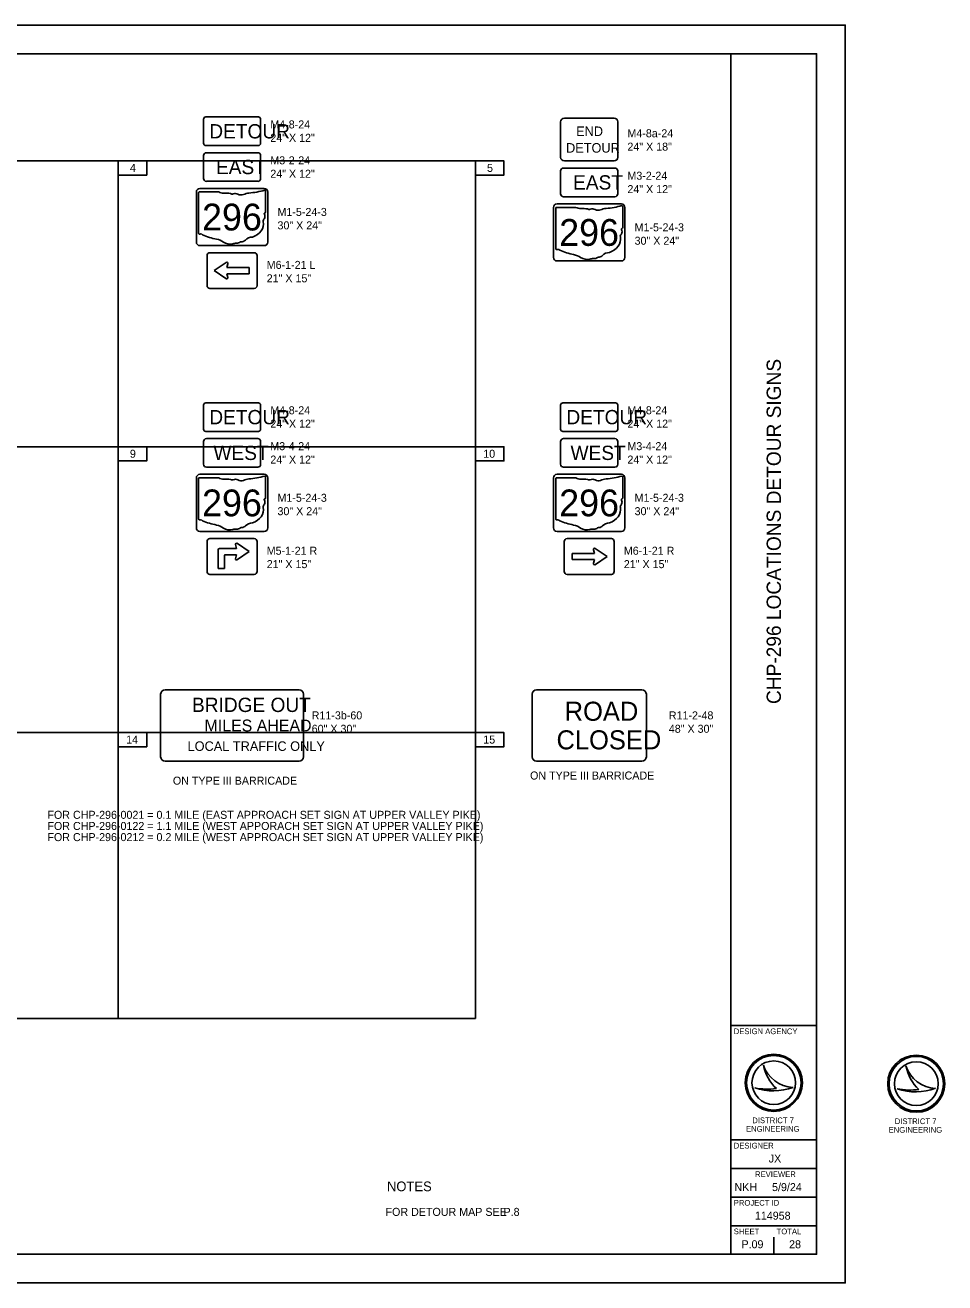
# Model space of a CAD drawing. Extents: x 0 to 715, y 0 to 440.
# Drawn here: x 393 to 714.9, y 0 to 440 of the extents above; entities that cross this region are included whole.
import ezdxf

# ---------------------------------------------------------------- set-up
doc = ezdxf.new("R2010")
doc.units = 0
for name, color, linetype in [('SC_Scratch1', 7, 'Continuous'), ('SH_Border', 7, 'Continuous'), ('SH_Cut_Line', 7, 'Continuous'), ('SH_Data', 7, 'Continuous'), ('SH_Text', 7, 'Continuous'), ('SN_P_Signs', 7, 'Continuous'), ('SN_P_Text', 7, 'Continuous')]:
    doc.layers.add(name, color=color, linetype=linetype)

msp = doc.modelspace()

# ---------------------------------------------------------------- linework, layer by layer
at = {"layer": 'SC_Scratch1'}
for p, q in [((375.54, 392.53), (550.54, 392.53)), ((425.54, 392.53), (425.54, 292.53)), ((550.54, 392.53), (550.54, 292.53)), ((375.54, 292.53), (550.54, 292.53)), ((425.54, 292.53), (425.54, 192.53)), ((550.54, 292.53), (550.54, 192.53)), ((375.54, 192.53), (550.54, 192.53)), ((425.54, 192.53), (425.54, 92.53)), ((550.54, 192.53), (550.54, 92.53)), ((375.54, 92.53), (550.54, 92.53))]:
    msp.add_line(p, q, dxfattribs=at)
at = {"layer": 'SH_Border'}
for p, q in [((640, 10), (640, 430)), ((640, 90), (670, 90)), ((640, 50), (670, 50)), ((640, 40), (670, 40)), ((640, 30), (670, 30)), ((640, 20), (670, 20))]:
    msp.add_line(p, q, dxfattribs=at)
msp.add_lwpolyline([(30, 430), (670, 430), (670, 10), (30, 10)], close=True, dxfattribs=at)
at = {"layer": 'SH_Cut_Line'}
msp.add_lwpolyline([(0, 0), (680, 0), (680, 440), (0, 440)], close=True, dxfattribs=at)
at = {"layer": 'SH_Data'}
for p, q in [((651.35, 76.19), (651.35, 76.19)), ((701.23, 75.87), (701.23, 75.87)), ((648.34, 68.19), (648.34, 68.19)), ((655, 70), (655, 70)), ((661.75, 68.37), (661.75, 68.37)), ((698.23, 67.87), (698.23, 67.87)), ((711.63, 68.05), (711.63, 68.05)), ((647.5, 13.5), (647.5, 13.5)), ((655, 10), (655, 16))]:
    msp.add_line(p, q, dxfattribs=at)
for centre, radius in [((655, 70), 10), ((655, 70), 9.54), ((655, 70), 9.54), ((704.88, 69.68), 10), ((704.88, 69.68), 9.54), ((704.88, 69.68), 9.54), ((655, 70), 7.64), ((704.88, 69.68), 7.64)]:
    msp.add_circle(centre, radius, dxfattribs=at)
for centre, radius, start, end in [((662.32, 79.95), 11.6, 198.9257, 198.9319), ((666.93, 79.4), 15.91, 191.6379, 191.6421), ((662.32, 79.95), 11.6, 198.9319, 267.1657), ((666.93, 79.4), 15.91, 191.6421, 226.0947), ((712.2, 79.63), 11.6, 198.9257, 198.9319), ((716.82, 79.08), 15.91, 191.6379, 191.6421), ((712.2, 79.63), 11.6, 198.9319, 267.1657), ((716.82, 79.08), 15.91, 191.6421, 226.0947), ((654.79, 87.4), 20.26, 251.4576, 290.0832), ((652.96, 93.09), 25.32, 259.4964, 259.4995), ((654.79, 87.4), 20.26, 251.4527, 251.4576), ((652.96, 93.09), 25.32, 259.4995, 276.6672), ((704.67, 87.08), 20.26, 251.4576, 290.0832), ((702.84, 92.77), 25.32, 259.4964, 259.4995), ((704.67, 87.08), 20.26, 251.4527, 251.4576), ((702.84, 92.77), 25.32, 259.4995, 276.6672)]:
    msp.add_arc(centre, radius, start, end, dxfattribs=at)
at = {"layer": 'SH_Text'}
for points in [[(425.54, 392.53), (435.54, 392.53), (435.54, 387.53), (425.54, 387.53)], [(550.54, 392.53), (560.54, 392.53), (560.54, 387.53), (550.54, 387.53)], [(425.54, 292.53), (435.54, 292.53), (435.54, 287.53), (425.54, 287.53)], [(550.54, 292.53), (560.54, 292.53), (560.54, 287.53), (550.54, 287.53)], [(425.54, 192.53), (435.54, 192.53), (435.54, 187.53), (425.54, 187.53)], [(550.54, 192.53), (560.54, 192.53), (560.54, 187.53), (550.54, 187.53)]]:
    msp.add_lwpolyline(points, close=True, dxfattribs=at)
at = {"layer": 'SN_P_Signs'}
for p, q in [((455.39, 386.37), (455.39, 394.37)), ((456.39, 395.37), (474.39, 395.37)), ((475.39, 394.37), (475.39, 386.37)), ((580.39, 380.99), (580.39, 388.99)), ((581.39, 389.99), (599.39, 389.99)), ((600.39, 388.99), (600.39, 380.99)), ((474.39, 385.37), (456.39, 385.37)), ((453.67, 381.39), (453.67, 367.16)), ((460.76, 381.64), (453.9, 381.64)), ((477.11, 374.55), (477.11, 381.99)), ((599.39, 379.99), (581.39, 379.99)), ((477.1, 374.55), (477.11, 374.55)), ((578.67, 376.02), (578.67, 361.79)), ((585.76, 376.26), (578.9, 376.26)), ((602.11, 369.17), (602.11, 376.61)), ((602.1, 369.17), (602.11, 369.17)), ((456.64, 359.37), (456.64, 348.87)), ((473.14, 360.37), (457.64, 360.37)), ((459.14, 354.12), (463.28, 356.96)), ((463.91, 356.49), (463.51, 355.21)), ((473.14, 360.37), (473.14, 360.37)), ((474.14, 348.87), (474.14, 359.37)), ((463.22, 351.32), (459.14, 354.12)), ((463.51, 355.21), (471.32, 355.21)), ((471.32, 353.02), (463.51, 353.02)), ((463.51, 353.02), (463.91, 351.74)), ((471.32, 355.21), (471.32, 353.02)), ((457.64, 347.87), (473.14, 347.87)), ((456.39, 295.37), (474.39, 295.37)), ((581.39, 295.37), (599.39, 295.37)), ((455.39, 286.37), (455.39, 294.37)), ((475.39, 294.37), (475.39, 286.37)), ((580.39, 286.37), (580.39, 294.37)), ((600.39, 294.37), (600.39, 286.37)), ((460.76, 281.64), (453.9, 281.64)), ((474.39, 285.37), (456.39, 285.37)), ((477.11, 274.55), (477.11, 281.99)), ((585.76, 281.64), (578.9, 281.64)), ((599.39, 285.37), (581.39, 285.37)), ((602.11, 274.55), (602.11, 281.99)), ((453.67, 281.39), (453.67, 267.16)), ((578.67, 281.39), (578.67, 267.16)), ((477.1, 274.55), (477.11, 274.55)), ((602.1, 274.55), (602.11, 274.55)), ((473.14, 260.37), (457.64, 260.37)), ((582.64, 260.37), (598.14, 260.37)), ((456.64, 259.37), (456.64, 248.87)), ((460.54, 249.9), (460.54, 256.46)), ((461.01, 256.93), (466.95, 256.93)), ((461.01, 256.93), (461.01, 256.93)), ((466.95, 256.93), (466.53, 258.33)), ((467.24, 258.63), (471.32, 255.83)), ((471.32, 255.83), (467.24, 253.04)), ((474.14, 248.87), (474.14, 259.37)), ((581.64, 248.87), (581.64, 259.37)), ((592.26, 255.21), (584.45, 255.21)), ((584.45, 255.21), (584.45, 253.02)), ((591.86, 256.49), (592.26, 255.21)), ((596.64, 254.12), (592.5, 256.96)), ((599.14, 259.37), (599.14, 248.87)), ((462.73, 254.43), (462.73, 249.9)), ((466.95, 254.74), (463.04, 254.74)), ((466.53, 253.33), (466.95, 254.74)), ((584.45, 253.02), (592.26, 253.02)), ((592.26, 253.02), (591.86, 251.74)), ((592.56, 251.32), (596.64, 254.12)), ((457.64, 247.87), (473.14, 247.87)), ((462.73, 249.9), (460.54, 249.9)), ((598.14, 247.87), (582.64, 247.87))]:
    msp.add_line(p, q, dxfattribs=at)
for points in [[(455.39, 407.07), (455.39, 398.67)], [(474.59, 407.87), (456.19, 407.87)], [(475.39, 398.67), (475.39, 407.07)], [(580.39, 406.19), (580.39, 393.79)], [(599.09, 407.49), (581.69, 407.49)], [(600.39, 393.79), (600.39, 406.19)], [(456.19, 397.87), (474.59, 397.87)], [(581.69, 392.49), (599.09, 392.49)], [(454.14, 382.87), (476.64, 382.87)], [(452.89, 364.12), (452.89, 381.62)], [(477.89, 381.62), (477.89, 364.12)], [(577.89, 358.74), (577.89, 376.24)], [(579.14, 377.49), (601.64, 377.49)], [(602.89, 376.24), (602.89, 358.74)], [(476.64, 362.87), (454.14, 362.87)], [(601.64, 357.49), (579.14, 357.49)], [(455.39, 307.07), (455.39, 298.67)], [(474.59, 307.87), (456.19, 307.87)], [(475.39, 298.67), (475.39, 307.07)], [(580.39, 307.07), (580.39, 298.67)], [(599.59, 307.87), (581.19, 307.87)], [(600.39, 298.67), (600.39, 307.07)], [(456.19, 297.87), (474.59, 297.87)], [(581.19, 297.87), (599.59, 297.87)], [(452.89, 264.12), (452.89, 281.62)], [(454.14, 282.87), (476.64, 282.87)], [(477.89, 281.62), (477.89, 264.12)], [(577.89, 264.12), (577.89, 281.62)], [(579.14, 282.87), (601.64, 282.87)], [(602.89, 281.62), (602.89, 264.12)], [(476.64, 262.87), (454.14, 262.87)], [(601.64, 262.87), (579.14, 262.87)], [(488.83, 207.49), (441.95, 207.49)], [(608.82, 207.49), (571.95, 207.49)], [(440.39, 205.93), (440.39, 184.05)], [(490.39, 184.05), (490.39, 205.93)], [(570.39, 205.92), (570.39, 184.06)], [(610.39, 184.06), (610.39, 205.92)], [(441.95, 182.49), (488.83, 182.49)], [(571.95, 182.49), (608.82, 182.49)]]:
    msp.add_lwpolyline(points, dxfattribs=at)
for centre, radius, start, end in [((456.19, 407.07), 0.8, 90, 180), ((474.59, 407.07), 0.8, 0, 90), ((581.69, 406.19), 1.3, 90, 180), ((599.09, 406.19), 1.3, 0, 90), ((456.19, 398.67), 0.8, 180, 270), ((474.59, 398.67), 0.8, 270, 0), ((456.39, 394.36), 1, 90, 180), ((474.39, 394.36), 1, 0, 90), ((581.69, 393.79), 1.3, 180, 270), ((599.09, 393.79), 1.3, 270, 0), ((581.39, 388.99), 1, 90, 180), ((599.39, 388.99), 1, 0, 90), ((454.14, 381.62), 1.25, 90, 180), ((456.39, 386.36), 1, 180, 270), ((474.39, 386.36), 1, 270, 0), ((476.64, 381.62), 1.25, 0, 90), ((581.39, 380.99), 1, 180, 270), ((599.39, 380.99), 1, 270, 0), ((579.14, 376.24), 1.25, 90, 180), ((601.64, 376.24), 1.25, 0, 90), ((454.14, 364.12), 1.25, 180, 270), ((476.64, 364.12), 1.25, 270, 0), ((457.64, 359.37), 1, 90, 180), ((463.51, 356.62), 0.417, 342.7954, 124.5888), ((473.14, 359.37), 1, 0, 90), ((579.14, 358.74), 1.25, 180, 270), ((601.64, 358.74), 1.25, 270, 0), ((457.64, 348.87), 1, 180, 270), ((463.51, 351.62), 0.417, 224.9904, 17.2046), ((473.14, 348.87), 1, 270, 0), ((456.19, 307.07), 0.8, 90, 180), ((474.59, 307.07), 0.8, 0, 90), ((581.19, 307.07), 0.8, 90, 180), ((599.59, 307.07), 0.8, 0, 90), ((456.19, 298.67), 0.8, 180, 270), ((456.39, 294.36), 1, 90, 180), ((474.39, 294.36), 1, 0, 90), ((474.59, 298.67), 0.8, 270, 0), ((581.19, 298.67), 0.8, 180, 270), ((581.39, 294.36), 1, 90, 180), ((599.39, 294.36), 1, 0, 90), ((599.59, 298.67), 0.8, 270, 0), ((456.39, 286.36), 1, 180, 270), ((474.39, 286.36), 1, 270, 0), ((581.39, 286.36), 1, 180, 270), ((599.39, 286.36), 1, 270, 0), ((454.14, 281.62), 1.25, 90, 180), ((476.64, 281.62), 1.25, 0, 90), ((579.14, 281.62), 1.25, 90, 180), ((601.64, 281.62), 1.25, 0, 90), ((454.14, 264.12), 1.25, 180, 270), ((476.64, 264.12), 1.25, 270, 0), ((579.14, 264.12), 1.25, 180, 270), ((601.64, 264.12), 1.25, 270, 0), ((457.64, 259.36), 1, 90, 180), ((473.14, 259.36), 1, 0, 90), ((582.64, 259.37), 1, 90, 180), ((598.14, 259.37), 1, 0, 90), ((461.01, 256.46), 0.469, 90, 180), ((466.95, 258.33), 0.417, 45.0001, 179.9983), ((592.26, 256.62), 0.417, 55.4112, 197.2046), ((463.04, 254.43), 0.312, 90, 180), ((466.95, 253.33), 0.417, 179.9983, 314.9999), ((592.26, 251.62), 0.417, 162.7954, 315.0096), ((457.64, 248.86), 1, 180, 270), ((473.14, 248.86), 1, 270, 0), ((582.64, 248.87), 1, 180, 270), ((598.14, 248.87), 1, 270, 360), ((441.95, 205.93), 1.56, 90, 180), ((488.83, 205.93), 1.56, 0, 90), ((571.95, 205.92), 1.57, 90, 180), ((608.82, 205.92), 1.57, 0, 90), ((441.95, 184.05), 1.56, 180, 270), ((488.83, 184.05), 1.56, 270, 0), ((571.95, 184.06), 1.57, 180, 270), ((608.82, 184.06), 1.57, 270, 0)]:
    msp.add_arc(centre, radius, start, end, dxfattribs=at)
for centre, major_axis, start_param, end_param in [((453.94, 381.42), (0.272, 0), 1.712693, 3.28349), ((462.4, 383.29), (2.63, 0), 4.042523, 4.731795), ((463.27, 373.65), (9.45, 0), 1.404758, 1.657858), ((465.42, 381.5), (0.76, 0), 3.836095, 5.185415), ((466.53, 379.85), (1.58, 0), 0.950623, 2.079405), ((468.57, 382.11), (1.9, 0), 4.081561, 5.145723), ((471.93, 377.29), (5, 0), 1.699011, 2.107814), ((468.76, 401.04), (24.85, 0), 4.814394, 5.042369), ((476.85, 382.02), (0.261, 0), 6.141152, 7.989035), ((477.05, 374), (0.404, 0), 1.883978, 3.671073), ((476.83, 374.52), (0.279, 0), 5.05454, 6.418171), ((578.94, 376.05), (0.272, 0), 1.712693, 3.28349), ((587.4, 377.91), (2.63, 0), 4.042523, 4.731795), ((588.27, 368.27), (9.45, 0), 1.404758, 1.657858), ((590.42, 376.12), (0.76, 0), 3.836095, 5.185415), ((591.53, 374.48), (1.58, 0), 0.950623, 2.079405), ((593.57, 376.73), (1.9, 0), 4.081561, 5.145723), ((596.93, 371.91), (5, 0), 1.699011, 2.107814), ((593.76, 395.66), (24.85, 0), 4.814394, 5.042369), ((601.85, 376.64), (0.261, 0), 6.141152, 7.989035), ((470.15, 370.48), (6.22, 0), 5.101752, 6.440018), ((478.04, 371.43), (1.76, 0), 2.387724, 3.262537), ((474.48, 373.06), (2.42, 0), 5.934695, 6.695948), ((453.94, 367.13), (0.274, 0), 3.00124, 4.508301), ((453.98, 368.59), (2.09, 0), 4.665946, 4.897461), ((454.41, 366.34), (0.754, 0), 0.519207, 1.627899), ((463.93, 379.13), (17.95, 0), 4.195997, 4.488961), ((472.77, 363.17), (3.4, 0), 1.647645, 2.488434), ((595.15, 365.11), (6.22, 0), 5.101752, 6.440018), ((603.04, 366.05), (1.76, 0), 2.387724, 3.262537), ((602.05, 368.62), (0.404, 0), 1.883978, 3.671073), ((599.48, 367.68), (2.42, 0), 5.934695, 6.695948), ((601.83, 369.14), (0.279, 0), 5.05454, 6.418171), ((458.57, 360.77), (5.62, 0), 0.823519, 1.323587), ((464.65, 366.27), (3.56, 0), 4.026481, 4.996735), ((466.71, 361.35), (2.93, 0), 1.495662, 1.94098), ((466.97, 365.21), (1.9, 0), 4.691044, 5.507374), ((468.69, 363.83), (0.535, 0), 1.147584, 2.315152), ((468.46, 365.78), (2.01, 0), 4.937069, 5.64225), ((578.94, 361.75), (0.274, 0), 3.00124, 4.508301), ((578.98, 363.21), (2.09, 0), 4.665946, 4.897461), ((579.41, 360.96), (0.754, 0), 0.519207, 1.627899), ((588.93, 373.75), (17.95, 0), 4.195997, 4.488961), ((583.57, 355.39), (5.62, 0), 0.823519, 1.323587), ((589.65, 360.89), (3.56, 0), 4.026481, 4.996735), ((591.71, 355.97), (2.93, 0), 1.495662, 1.94098), ((591.97, 359.83), (1.9, 0), 4.691044, 5.507374), ((593.69, 358.45), (0.535, 0), 1.147584, 2.315152), ((593.46, 360.41), (2.01, 0), 4.937069, 5.64225), ((597.77, 357.79), (3.4, 0), 1.647645, 2.488434), ((453.94, 281.42), (0.272, 0), 1.712693, 3.28349), ((462.4, 283.29), (2.63, 0), 4.042523, 4.731795), ((468.76, 301.04), (24.85, 0), 4.814394, 5.042369), ((476.85, 282.02), (0.261, 0), 6.141152, 7.989035), ((578.94, 281.42), (0.272, 0), 1.712693, 3.28349), ((587.4, 283.29), (2.63, 0), 4.042523, 4.731795), ((593.76, 301.04), (24.85, 0), 4.814394, 5.042369), ((601.85, 282.02), (0.261, 0), 6.141152, 7.989035), ((463.27, 273.65), (9.45, 0), 1.404758, 1.657858), ((465.42, 281.5), (0.76, 0), 3.836095, 5.185415), ((466.53, 279.85), (1.58, 0), 0.950623, 2.079405), ((468.57, 282.11), (1.9, 0), 4.081561, 5.145723), ((471.93, 277.29), (5, 0), 1.699011, 2.107814), ((588.27, 273.65), (9.45, 0), 1.404758, 1.657858), ((590.42, 281.5), (0.76, 0), 3.836095, 5.185415), ((591.53, 279.85), (1.58, 0), 0.950623, 2.079405), ((593.57, 282.11), (1.9, 0), 4.081561, 5.145723), ((596.93, 277.29), (5, 0), 1.699011, 2.107814), ((477.05, 274), (0.404, 0), 1.883978, 3.671073), ((474.48, 273.06), (2.42, 0), 5.934695, 6.695948), ((476.83, 274.52), (0.279, 0), 5.05454, 6.418171), ((602.05, 274), (0.404, 0), 1.883978, 3.671073), ((599.48, 273.06), (2.42, 0), 5.934695, 6.695948), ((601.83, 274.52), (0.279, 0), 5.05454, 6.418171), ((470.15, 270.48), (6.22, 0), 5.101752, 6.440018), ((478.04, 271.43), (1.76, 0), 2.387724, 3.262537), ((595.15, 270.48), (6.22, 0), 5.101752, 6.440018), ((603.04, 271.43), (1.76, 0), 2.387724, 3.262537), ((453.94, 267.13), (0.274, 0), 3.00124, 4.508301), ((453.98, 268.59), (2.09, 0), 4.665946, 4.897461), ((454.41, 266.34), (0.754, 0), 0.519207, 1.627899), ((463.93, 279.13), (17.95, 0), 4.195997, 4.488961), ((458.57, 260.77), (5.62, 0), 0.823519, 1.323587), ((464.65, 266.27), (3.56, 0), 4.026481, 4.996735), ((466.97, 265.21), (1.9, 0), 4.691044, 5.507374), ((468.69, 263.83), (0.535, 0), 1.147584, 2.315152), ((468.46, 265.78), (2.01, 0), 4.937069, 5.64225), ((472.77, 263.17), (3.4, 0), 1.647645, 2.488434), ((578.94, 267.13), (0.274, 0), 3.00124, 4.508301), ((578.98, 268.59), (2.09, 0), 4.665946, 4.897461), ((579.41, 266.34), (0.754, 0), 0.519207, 1.627899), ((588.93, 279.13), (17.95, 0), 4.195997, 4.488961), ((583.57, 260.77), (5.62, 0), 0.823519, 1.323587), ((589.65, 266.27), (3.56, 0), 4.026481, 4.996735), ((591.97, 265.21), (1.9, 0), 4.691044, 5.507374), ((593.69, 263.83), (0.535, 0), 1.147584, 2.315152), ((593.46, 265.78), (2.01, 0), 4.937069, 5.64225), ((597.77, 263.17), (3.4, 0), 1.647645, 2.488434), ((466.71, 261.35), (2.93, 0), 1.495662, 1.94098), ((591.71, 261.35), (2.93, 0), 1.495662, 1.94098)]:
    msp.add_ellipse(centre, major_axis=major_axis, ratio=0.8, start_param=start_param, end_param=end_param, dxfattribs=at)

# ---------------------------------------------------------------- texts
at = {"layer": 'SH_Data'}
msp.add_text('CHP-296 LOCATIONS DETOUR SIGNS', height=5, rotation=90, dxfattribs=at).set_placement((657.5, 202.5))
for s, height, p in [('DESIGN AGENCY', 2, (641, 87)), ('DESIGNER', 2, (641, 47)), ('JX', 2.8, (653.23, 42.1)), ('REVIEWER', 2, (648.44, 37)), ('NKH', 2.8, (641.24, 32.1)), ('5/9/24', 2.8, (654.39, 32.1)), ('PROJECT ID', 2, (641, 27)), ('114958', 2.8, (648.39, 22.1)), ('SHEET', 2, (641, 17)), ('TOTAL', 2, (656, 17)), ('P.09', 2.8, (643.68, 12.1)), ('28', 2.8, (660.36, 12.1))]:
    msp.add_text(s, height=height, dxfattribs=at).set_placement(p)
at = {"layer": 'SH_Text'}
for s, height, p in [('4', 2.8, (429.63, 388.66)), ('5', 2.8, (554.63, 388.66)), ('9', 2.8, (429.63, 288.66)), ('10', 2.8, (553.31, 288.66)), ('14', 2.8, (428.31, 188.66)), ('15', 2.8, (553.31, 188.66)), ('DISTRICT 7', 2, (647.48, 55.85)), ('DISTRICT 7', 2, (697.36, 55.53)), ('ENGINEERING', 2, (645.3, 52.85)), ('ENGINEERING', 2, (695.19, 52.53)), ('NOTES', 3.4, (519.61, 32.05)), ('FOR DETOUR MAP SEE', 2.8, (519.1, 23.43)), ('P.8', 2.8, (560.4, 23.43))]:
    msp.add_text(s, height=height, dxfattribs=at).set_placement(p)
at = {"layer": 'SN_P_Signs'}
for s, height, p in [('DETOUR', 5, (457.42, 400.37)), ('END', 3.333, (585.83, 401.22)), ('DETOUR', 3.333, (582.29, 395.4)), ('EAST', 5, (459.75, 387.87)), ('EAST', 5, (584.75, 382.49)), ('296', 9.375, (454.89, 368.17)), ('296', 9.375, (579.89, 362.79)), ('DETOUR', 5, (457.42, 300.37)), ('DETOUR', 5, (582.42, 300.37)), ('WEST', 5, (458.86, 287.87)), ('WEST', 5, (583.86, 287.87)), ('296', 9.375, (454.89, 268.17)), ('296', 9.375, (579.89, 268.17)), ('BRIDGE OUT', 5, (451.36, 199.71)), ('ROAD', 6.667, (581.81, 196.64)), ('MILES AHEAD', 4.1667, (455.74, 192.9)), ('LOCAL TRAFFIC ONLY', 3.3333, (449.81, 186.1)), ('CLOSED', 6.667, (578.95, 186.64))]:
    msp.add_text(s, height=height, dxfattribs=at).set_placement(p)
at = {"layer": 'SN_P_Text'}
for s, p in [('M4-8-24', (478.77, 403.87)), ('24" X 12"', (478.77, 399.18)), ('M4-8a-24', (603.77, 400.78)), ('24" X 18"', (603.77, 396.09)), ('M3-2-24', (478.77, 391.31)), ('24" X 12"', (478.77, 386.62)), ('M3-2-24', (603.77, 385.93)), ('24" X 12"', (603.77, 381.24)), ('M1-5-24-3', (481.28, 373.25)), ('30" X 24"', (481.28, 368.56)), ('M1-5-24-3', (606.28, 367.87)), ('30" X 24"', (606.28, 363.18)), ('M6-1-21 L', (477.51, 354.73)), ('21" X 15"', (477.51, 350.04)), ('M4-8-24', (478.77, 303.87)), ('M4-8-24', (603.77, 303.87)), ('24" X 12"', (478.77, 299.18)), ('24" X 12"', (603.77, 299.18)), ('M3-4-24', (478.77, 291.31)), ('M3-4-24', (603.77, 291.31)), ('24" X 12"', (478.77, 286.62)), ('24" X 12"', (603.77, 286.62)), ('M1-5-24-3', (481.28, 273.25)), ('M1-5-24-3', (606.28, 273.25)), ('30" X 24"', (481.28, 268.56)), ('30" X 24"', (606.28, 268.56)), ('M5-1-21 R', (477.51, 254.73)), ('M6-1-21 R', (602.51, 254.73)), ('21" X 15"', (477.51, 250.04)), ('21" X 15"', (602.51, 250.04)), ('R11-3b-60', (493.26, 197.13)), ('R11-2-48', (618.26, 197.13)), ('60" X 30"', (493.26, 192.44)), ('48" X 30"', (618.26, 192.44)), ('ON TYPE III BARRICADE', (444.67, 174.29)), ('ON TYPE III BARRICADE', (569.69, 176.09)), ('FOR CHP-296-0021 = 0.1 MILE (EAST APPROACH SET SIGN AT UPPER VALLEY PIKE)', (400.75, 162.34)), ('FOR CHP-296-0122 = 1.1 MILE (WEST APPORACH SET SIGN AT UPPER VALLEY PIKE)', (400.75, 158.44)), ('FOR CHP-296-0212 = 0.2 MILE (WEST APPROACH SET SIGN AT UPPER VALLEY PIKE)', (400.75, 154.54))]:
    msp.add_text(s, height=2.8, dxfattribs=at).set_placement(p)

doc.saveas('drawing.dxf')
